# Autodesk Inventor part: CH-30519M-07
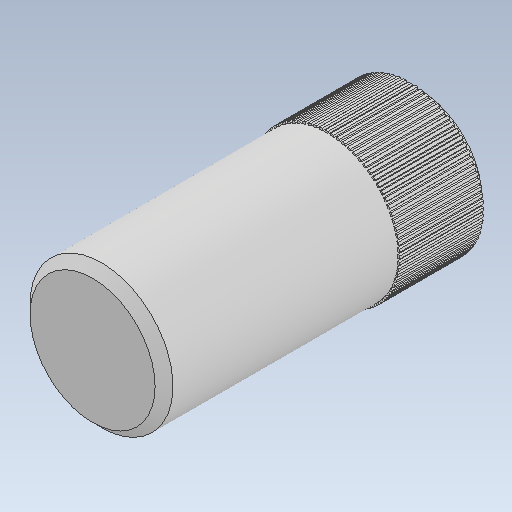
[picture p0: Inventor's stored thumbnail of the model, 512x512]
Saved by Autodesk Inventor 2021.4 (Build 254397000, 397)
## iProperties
Created: 2017-11
Part Number: CH-30519M-07
Material: Ogólny
Document SubType Name: Modeling
Designer: user
Density: 1 g/cm^3
Appearance: Domyślna
Author: user
Revision Number: ÈÎºÎ
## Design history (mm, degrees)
feature "ÕóÁÐ(Ô²ÖÜ)1"
node "Bryła1"
